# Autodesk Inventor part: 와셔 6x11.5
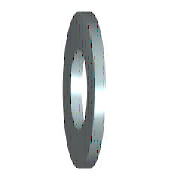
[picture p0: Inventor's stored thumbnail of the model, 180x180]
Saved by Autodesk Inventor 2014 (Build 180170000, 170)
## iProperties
IsCustomPart: 1
Created: 2012-02
Part Number: 와셔 6x11.5
Material: 강철, 연강
Description: 평면 와셔
Document SubType Name: Modeling
Standard: KS B 1326
Designer: mduedu
Standards Organization: KS
Language: ko-KR
Size Designation: 6x11.5
Categories: <MemberInstance><Categories><Category DisplayName="조임쇠" InternalName="e4da775c-781d-43d5-af7c-5136215cf5a6" Mnemonic="FSTN"><Category DisplayName="와셔" InternalN
Density: 7.86 g/cm^3
Mass: 0.901687 g
Surface Area: 2.33373 cm^2
Volume: 0.114718 cm^3
Appearance: 주황색
Author: mduedu
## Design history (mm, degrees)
sketch "스케치"
  geometry: C1 r 5.75 at (0, 0); C2 r 3.2 at (0, 0); 1 further point
  constraints: 2 centre point, 2 coincident
  dimensions: "d0" = 6.4 diameter of C2 (= SD1); "d1" = 11.5 diameter of C1 (= SD2)
extrude "본체" new body sketch "스케치" distance "d2" = 1.6 (= SD); taper "d3" = 0 deg
workaxis "Work Axis1"
workplane "Work Plane1"
body "Solid1"
other parameters: "SD1" = 6.4 [user parameter; used in 1 equation term], "SD2" = 11.5 [user parameter; used in 1 equation term], "SD" = 1.6 [user parameter; used in 1 equation term], "d4" = 0, "d5" = 0, "d6" = 0, "d7" = 0, "NND" = 6 [user parameter]
